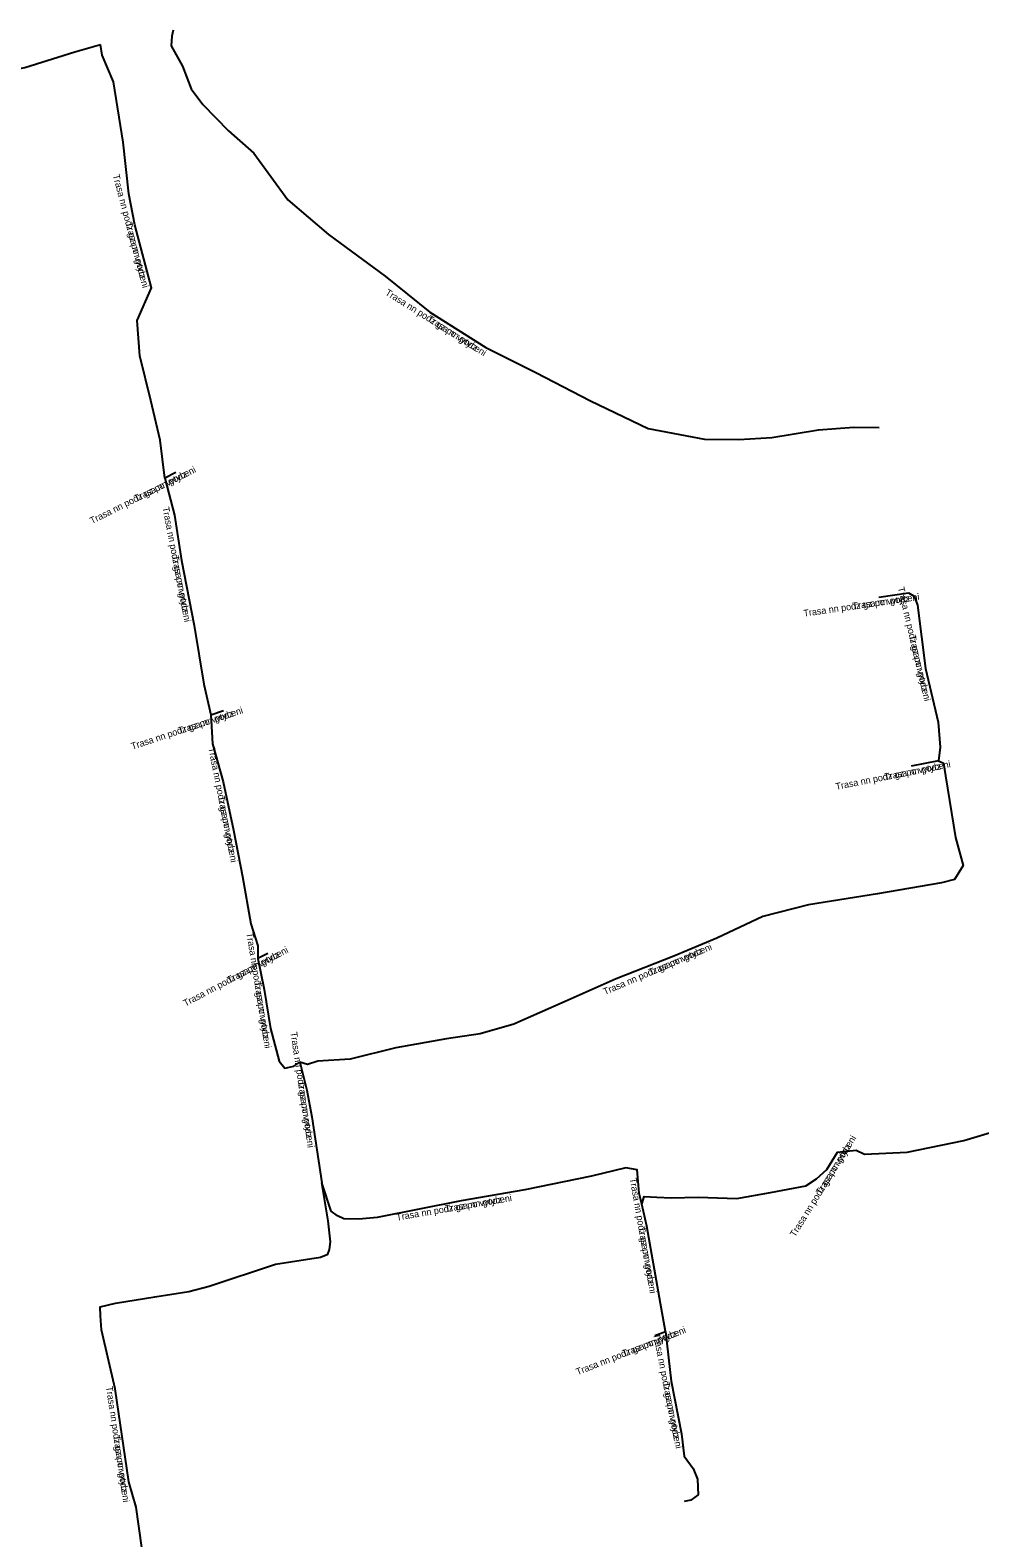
# Model space of a CAD drawing. Extents: x -876384 to -875659, y -1020218 to -1019588.
# Drawn here: x -875879 to -875808.4, y -1019934.5 to -1019822.5 of the extents above; entities that cross this region are included whole.
import ezdxf

# ---------------------------------------------------------------- set-up
doc = ezdxf.new("R2010")
doc.units = 0
doc.layers.add('Popiskový text - Ostatní atributy Trasy', color=7, linetype='Continuous')
doc.layers.add('Spojnice NN', color=7, linetype='Continuous')

msp = doc.modelspace()

# ---------------------------------------------------------------- linework, layer by layer
at = {"layer": 'Spojnice NN'}
for points in [[(-875868.35, -1019822.47), (-875868.46, -1019822.91), (-875868.5, -1019823.63), (-875867.67, -1019825.15), (-875867.01, -1019826.84), (-875866.14, -1019827.99), (-875864.23, -1019829.96), (-875862.35, -1019831.61), (-875859.83, -1019835.07), (-875856.81, -1019837.66), (-875852.6, -1019840.74), (-875849.29, -1019843.43), (-875845.13, -1019846.04), (-875841.4, -1019847.9), (-875837.34, -1019850), (-875833.06, -1019852.07), (-875828.86, -1019852.85), (-875826.32, -1019852.87), (-875823.87, -1019852.73), (-875820.4, -1019852.15), (-875817.78, -1019851.95), (-875815.88, -1019851.99)], [(-875868.35, -1019822.47), (-875868.46, -1019822.91), (-875868.5, -1019823.63), (-875867.67, -1019825.15), (-875867.01, -1019826.84), (-875866.14, -1019827.99), (-875864.23, -1019829.96), (-875862.35, -1019831.61), (-875859.83, -1019835.07), (-875856.81, -1019837.66), (-875852.6, -1019840.74), (-875849.29, -1019843.43), (-875845.13, -1019846.04), (-875841.4, -1019847.9), (-875837.34, -1019850), (-875833.06, -1019852.07), (-875828.86, -1019852.85), (-875826.32, -1019852.87), (-875823.87, -1019852.73), (-875820.4, -1019852.15), (-875817.78, -1019851.95), (-875815.88, -1019851.99)], [(-875885.35, -1019839.9), (-875884.28, -1019839.2), (-875884.49, -1019837.08), (-875885.1, -1019833.8), (-875885.54, -1019830.94), (-875885.92, -1019828.56), (-875886.28, -1019826.79), (-875886.18, -1019826.25), (-875885.26, -1019826.07), (-875882.95, -1019825.99), (-875879.38, -1019825.25), (-875875.66, -1019824.08), (-875873.75, -1019823.54)], [(-875885.35, -1019839.9), (-875884.28, -1019839.2), (-875884.49, -1019837.08), (-875885.1, -1019833.8), (-875885.54, -1019830.94), (-875885.92, -1019828.56), (-875886.28, -1019826.79), (-875886.18, -1019826.25), (-875885.26, -1019826.07), (-875882.95, -1019825.99), (-875879.38, -1019825.25), (-875875.66, -1019824.08), (-875873.75, -1019823.54)], [(-875868.98, -1019855.74), (-875869.32, -1019852.92), (-875870.02, -1019849.97), (-875870.84, -1019846.67), (-875871.03, -1019844.03), (-875869.96, -1019841.62), (-875871.2, -1019836.92), (-875871.64, -1019834.63), (-875872.07, -1019830.78), (-875872.79, -1019826.32), (-875873.63, -1019824.34), (-875873.75, -1019823.54)], [(-875868.98, -1019855.74), (-875869.32, -1019852.92), (-875870.02, -1019849.97), (-875870.84, -1019846.67), (-875871.03, -1019844.03), (-875869.96, -1019841.62), (-875871.2, -1019836.92), (-875871.64, -1019834.63), (-875872.07, -1019830.78), (-875872.79, -1019826.32), (-875873.63, -1019824.34), (-875873.75, -1019823.54)], [(-875868.16, -1019855.33), (-875868.98, -1019855.74)], [(-875868.16, -1019855.33), (-875868.98, -1019855.74)], [(-875868.98, -1019855.74), (-875868.26, -1019858.5), (-875867.73, -1019861.86), (-875866.8, -1019866.7), (-875866.07, -1019871.05), (-875865.56, -1019873.32)], [(-875868.98, -1019855.74), (-875868.26, -1019858.5), (-875867.73, -1019861.86), (-875866.8, -1019866.7), (-875866.07, -1019871.05), (-875865.56, -1019873.32)], [(-875815.92, -1019864.58), (-875813.7, -1019864.26)], [(-875815.92, -1019864.58), (-875813.7, -1019864.26)], [(-875813.7, -1019864.26), (-875813.28, -1019864.51), (-875813.04, -1019865.19), (-875812.44, -1019869.89), (-875811.5, -1019873.88), (-875811.35, -1019875.74), (-875811.49, -1019876.75)], [(-875813.7, -1019864.26), (-875813.28, -1019864.51), (-875813.04, -1019865.19), (-875812.44, -1019869.89), (-875811.5, -1019873.88), (-875811.35, -1019875.74), (-875811.49, -1019876.75)], [(-875865.56, -1019873.32), (-875864.62, -1019873.01)], [(-875865.56, -1019873.32), (-875864.62, -1019873.01)], [(-875865.56, -1019873.32), (-875865.43, -1019875.49), (-875864.63, -1019878.32), (-875863.88, -1019881.89), (-875863.2, -1019885.34), (-875862.57, -1019888.86), (-875862.05, -1019890.49), (-875862.07, -1019891.44)], [(-875865.56, -1019873.32), (-875865.43, -1019875.49), (-875864.63, -1019878.32), (-875863.88, -1019881.89), (-875863.2, -1019885.34), (-875862.57, -1019888.86), (-875862.05, -1019890.49), (-875862.07, -1019891.44)], [(-875811.49, -1019876.75), (-875811.1, -1019876.91), (-875810.96, -1019877.87), (-875810.21, -1019882.45), (-875809.66, -1019884.52), (-875810.29, -1019885.57), (-875811.27, -1019885.8), (-875816.01, -1019886.62), (-875821.14, -1019887.45), (-875824.54, -1019888.3), (-875827.96, -1019889.91), (-875831.16, -1019891.27), (-875835.44, -1019892.95), (-875839.23, -1019894.63), (-875843.04, -1019896.32), (-875845.55, -1019897.04), (-875848.05, -1019897.4), (-875851.81, -1019898.08), (-875855.19, -1019898.92), (-875857.61, -1019899.06), (-875858.37, -1019899.31), (-875858.94, -1019899.13)], [(-875811.49, -1019876.75), (-875811.1, -1019876.91), (-875810.96, -1019877.87), (-875810.21, -1019882.45), (-875809.66, -1019884.52), (-875810.29, -1019885.57), (-875811.27, -1019885.8), (-875816.01, -1019886.62), (-875821.14, -1019887.45), (-875824.54, -1019888.3), (-875827.96, -1019889.91), (-875831.16, -1019891.27), (-875835.44, -1019892.95), (-875839.23, -1019894.63), (-875843.04, -1019896.32), (-875845.55, -1019897.04), (-875848.05, -1019897.4), (-875851.81, -1019898.08), (-875855.19, -1019898.92), (-875857.61, -1019899.06), (-875858.37, -1019899.31), (-875858.94, -1019899.13)], [(-875811.49, -1019876.75), (-875813.51, -1019877.15)], [(-875811.49, -1019876.75), (-875813.51, -1019877.15)], [(-875861.33, -1019891.05), (-875862.07, -1019891.44)], [(-875861.33, -1019891.05), (-875862.07, -1019891.44)], [(-875862.07, -1019891.44), (-875861.59, -1019893.73), (-875861.13, -1019896.62), (-875860.48, -1019899.05), (-875860.05, -1019899.57), (-875859.39, -1019899.43), (-875858.94, -1019899.13)], [(-875862.07, -1019891.44), (-875861.59, -1019893.73), (-875861.13, -1019896.62), (-875860.48, -1019899.05), (-875860.05, -1019899.57), (-875859.39, -1019899.43), (-875858.94, -1019899.13)], [(-875858.94, -1019899.13), (-875858.41, -1019901.22), (-875858.04, -1019903.19), (-875857.3, -1019908.09)], [(-875858.94, -1019899.13), (-875858.41, -1019901.22), (-875858.04, -1019903.19), (-875857.3, -1019908.09)], [(-875833.52, -1019909.68), (-875833.35, -1019909.11), (-875832.4, -1019909.15), (-875831.35, -1019909.21), (-875829.35, -1019909.17), (-875826.46, -1019909.25), (-875823.96, -1019908.81), (-875821.35, -1019908.32), (-875820.55, -1019907.79), (-875819.78, -1019907.1), (-875818.99, -1019905.82), (-875817.61, -1019905.68), (-875816.97, -1019905.97), (-875813.82, -1019905.83), (-875809.59, -1019904.94), (-875806.12, -1019903.91), (-875804.33, -1019903.83), (-875803.91, -1019903.89), (-875803.59, -1019904.04)], [(-875833.52, -1019909.68), (-875833.35, -1019909.11), (-875832.4, -1019909.15), (-875831.35, -1019909.21), (-875829.35, -1019909.17), (-875826.46, -1019909.25), (-875823.96, -1019908.81), (-875821.35, -1019908.32), (-875820.55, -1019907.79), (-875819.78, -1019907.1), (-875818.99, -1019905.82), (-875817.61, -1019905.68), (-875816.97, -1019905.97), (-875813.82, -1019905.83), (-875809.59, -1019904.94), (-875806.12, -1019903.91), (-875804.33, -1019903.83), (-875803.91, -1019903.89), (-875803.59, -1019904.04)], [(-875833.52, -1019909.68), (-875833.72, -1019908.87), (-875833.88, -1019907.13), (-875834.72, -1019906.98), (-875837.26, -1019907.61), (-875842.22, -1019908.62), (-875846.96, -1019909.43), (-875853.2, -1019910.68), (-875854.55, -1019910.79), (-875855.68, -1019910.77), (-875856.14, -1019910.55), (-875856.61, -1019910.2), (-875857.3, -1019908.09)], [(-875833.52, -1019909.68), (-875833.72, -1019908.87), (-875833.88, -1019907.13), (-875834.72, -1019906.98), (-875837.26, -1019907.61), (-875842.22, -1019908.62), (-875846.96, -1019909.43), (-875853.2, -1019910.68), (-875854.55, -1019910.79), (-875855.68, -1019910.77), (-875856.14, -1019910.55), (-875856.61, -1019910.2), (-875857.3, -1019908.09)], [(-875880.92, -1019938.2), (-875877.07, -1019937.47), (-875874.01, -1019936.95), (-875871.98, -1019936.6), (-875871.05, -1019936.13), (-875870.78, -1019935.83), (-875870.69, -1019935.18), (-875871.1, -1019932.2), (-875871.64, -1019930.3), (-875872.67, -1019923.39), (-875873.67, -1019919.02), (-875873.75, -1019917.98), (-875873.77, -1019917.31), (-875872.64, -1019917.04), (-875869.71, -1019916.57), (-875867.18, -1019916.17), (-875865.68, -1019915.78), (-875860.74, -1019914.13), (-875857.41, -1019913.62), (-875856.86, -1019913.39), (-875856.73, -1019913.06), (-875856.65, -1019912.47), (-875856.84, -1019910.93), (-875857.3, -1019908.09)], [(-875880.92, -1019938.2), (-875877.07, -1019937.47), (-875874.01, -1019936.95), (-875871.98, -1019936.6), (-875871.05, -1019936.13), (-875870.78, -1019935.83), (-875870.69, -1019935.18), (-875871.1, -1019932.2), (-875871.64, -1019930.3), (-875872.67, -1019923.39), (-875873.67, -1019919.02), (-875873.75, -1019917.98), (-875873.77, -1019917.31), (-875872.64, -1019917.04), (-875869.71, -1019916.57), (-875867.18, -1019916.17), (-875865.68, -1019915.78), (-875860.74, -1019914.13), (-875857.41, -1019913.62), (-875856.86, -1019913.39), (-875856.73, -1019913.06), (-875856.65, -1019912.47), (-875856.84, -1019910.93), (-875857.3, -1019908.09)], [(-875831.78, -1019919.13), (-875832.21, -1019916.64), (-875833.15, -1019911.31), (-875833.52, -1019909.68)], [(-875831.78, -1019919.13), (-875832.21, -1019916.64), (-875833.15, -1019911.31), (-875833.52, -1019909.68)], [(-875832.57, -1019919.44), (-875831.78, -1019919.13)], [(-875832.57, -1019919.44), (-875831.78, -1019919.13)], [(-875831.78, -1019919.13), (-875831.34, -1019922.83), (-875830.57, -1019926.73), (-875830.39, -1019928.41), (-875829.7, -1019929.32), (-875829.39, -1019930.11), (-875829.33, -1019931.27), (-875829.89, -1019931.67), (-875830.39, -1019931.78)], [(-875831.78, -1019919.13), (-875831.34, -1019922.83), (-875830.57, -1019926.73), (-875830.39, -1019928.41), (-875829.7, -1019929.32), (-875829.39, -1019930.11), (-875829.33, -1019931.27), (-875829.89, -1019931.67), (-875830.39, -1019931.78)]]:
    msp.add_lwpolyline(points, dxfattribs=at)

# ---------------------------------------------------------------- texts
at = {"layer": 'Popiskový text - Ostatní atributy Trasy'}
for s, rotation, p in [('Trasa nn podz gz po vytyceni', 284.7796, (-875872.84, -1019833.25)), ('Trasa nn podz', 284.7796, (-875871.9, -1019836.81)), ('Trasa nn podz gz po vytyceni', 327.8957, (-875852.64, -1019842.09)), ('Trasa nn podz', 327.8957, (-875849.52, -1019844.05)), ('Trasa nn podz gz po vytyceni', 26.5651, (-875874.39, -1019859.17)), ('Trasa nn podz', 26.5651, (-875871.09, -1019857.52)), ('Trasa nn podz gz po vytyceni', 280.8767, (-875869.15, -1019857.93)), ('Trasa nn podz', 280.8767, (-875868.45, -1019861.55)), ('Trasa nn podz gz po vytyceni', 8.2024, (-875821.48, -1019866.04)), ('Trasa nn podz', 8.2024, (-875817.83, -1019865.51)), ('Trasa nn podz gz po vytyceni', 283.2565, (-875814.52, -1019863.89)), ('Trasa nn podz', 283.2565, (-875813.68, -1019867.48)), ('Trasa nn podz gz po vytyceni', 18.2519, (-875871.38, -1019875.92)), ('Trasa nn podz', 18.2519, (-875867.88, -1019874.77)), ('Trasa nn podz gz po vytyceni', 281.1502, (-875865.74, -1019875.8)), ('Trasa nn podz gz po vytyceni', 11.2008, (-875819.08, -1019878.91)), ('Trasa nn podz', 11.2008, (-875815.46, -1019878.2)), ('Trasa nn podz', 281.1502, (-875865.03, -1019879.41)), ('Trasa nn podz gz po vytyceni', 279.0439, (-875862.91, -1019889.55)), ('Trasa nn podz gz po vytyceni', 23.0255, (-875836.27, -1019894.15)), ('Trasa nn podz gz po vytyceni', 27.7904, (-875867.44, -1019895.01)), ('Trasa nn podz', 27.7904, (-875864.18, -1019893.29)), ('Trasa nn podz', 23.0255, (-875832.88, -1019892.71)), ('Trasa nn podz', 279.0439, (-875862.33, -1019893.19)), ('Trasa nn podz gz po vytyceni', 278.5879, (-875859.64, -1019896.92)), ('Trasa nn podz', 278.5879, (-875859.09, -1019900.57)), ('Trasa nn podz gz po vytyceni', 58.3176, (-875822.14, -1019912.16)), ('Trasa nn podz', 58.3176, (-875820.2, -1019909.02)), ('Trasa nn podz gz po vytyceni', 280.0018, (-875834.43, -1019907.78)), ('Trasa nn podz gz po vytyceni', 9.6974, (-875851.73, -1019910.91)), ('Trasa nn podz', 9.6974, (-875848.1, -1019910.28)), ('Trasa nn podz', 280.0018, (-875833.79, -1019911.41)), ('Trasa nn podz gz po vytyceni', 21.4253, (-875838.3, -1019922.39)), ('Trasa nn podz', 21.4253, (-875834.87, -1019921.04)), ('Trasa nn podz gz po vytyceni', 281.1686, (-875832.69, -1019919.34)), ('Trasa nn podz gz po vytyceni', 278.478, (-875873.35, -1019923.25)), ('Trasa nn podz', 281.1686, (-875831.98, -1019922.95)), ('Trasa nn podz', 278.478, (-875872.81, -1019926.89))]:
    msp.add_text(s, height=0.5, rotation=rotation, dxfattribs=at).set_placement(p)

doc.saveas('drawing.dxf')
